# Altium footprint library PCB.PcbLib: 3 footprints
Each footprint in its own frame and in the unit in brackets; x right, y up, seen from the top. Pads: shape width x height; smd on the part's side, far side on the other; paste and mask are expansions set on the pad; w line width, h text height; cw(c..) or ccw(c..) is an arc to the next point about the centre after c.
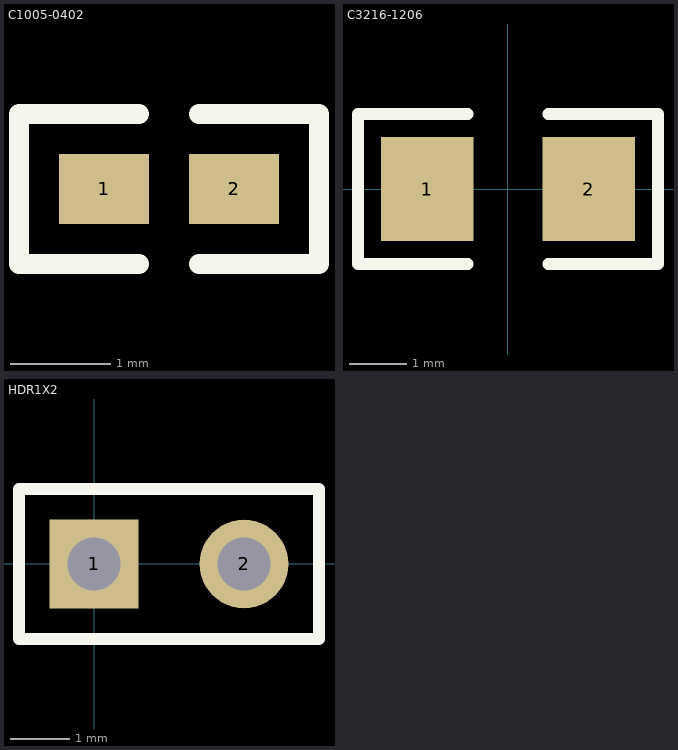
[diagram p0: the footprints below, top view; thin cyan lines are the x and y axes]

## C1005-0402 [mm]
pads (2):
  rect 0.9x0.7 smd: 1(1269.35,1270.012) 2(1270.65,1270.012)
Top Overlay:
  lines w0.2: 1269.7,1269.262 1268.5,1269.262 1268.5,1270.762 1269.7,1270.762 ; 1270.3,1269.262 1271.5,1269.262 1271.5,1270.762 1270.3,1270.762

## C3216-1206 [mm]
pads (2):
  rect 1.6x1.8 smd: 1(-1.397,0.008) 2(1.403,0.008)
Top Overlay:
  lines w0.2: -0.697,-1.292 -2.597,-1.292 -2.597,1.308 -0.697,1.308 ; 0.703,-1.292 2.603,-1.292 2.603,1.308 0.703,1.308

## HDR1X2 [mm]
pads (2):
  rect 1.5x1.5 hole 0.9: 1(-0.002,-0.002)
  round 1.5 hole 0.9: 2(2.538,-0.002)
Top Overlay:
  lines w0.2: -1.272,-1.272 -1.272,1.268 3.808,1.268 3.808,-1.272 -1.272,-1.272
